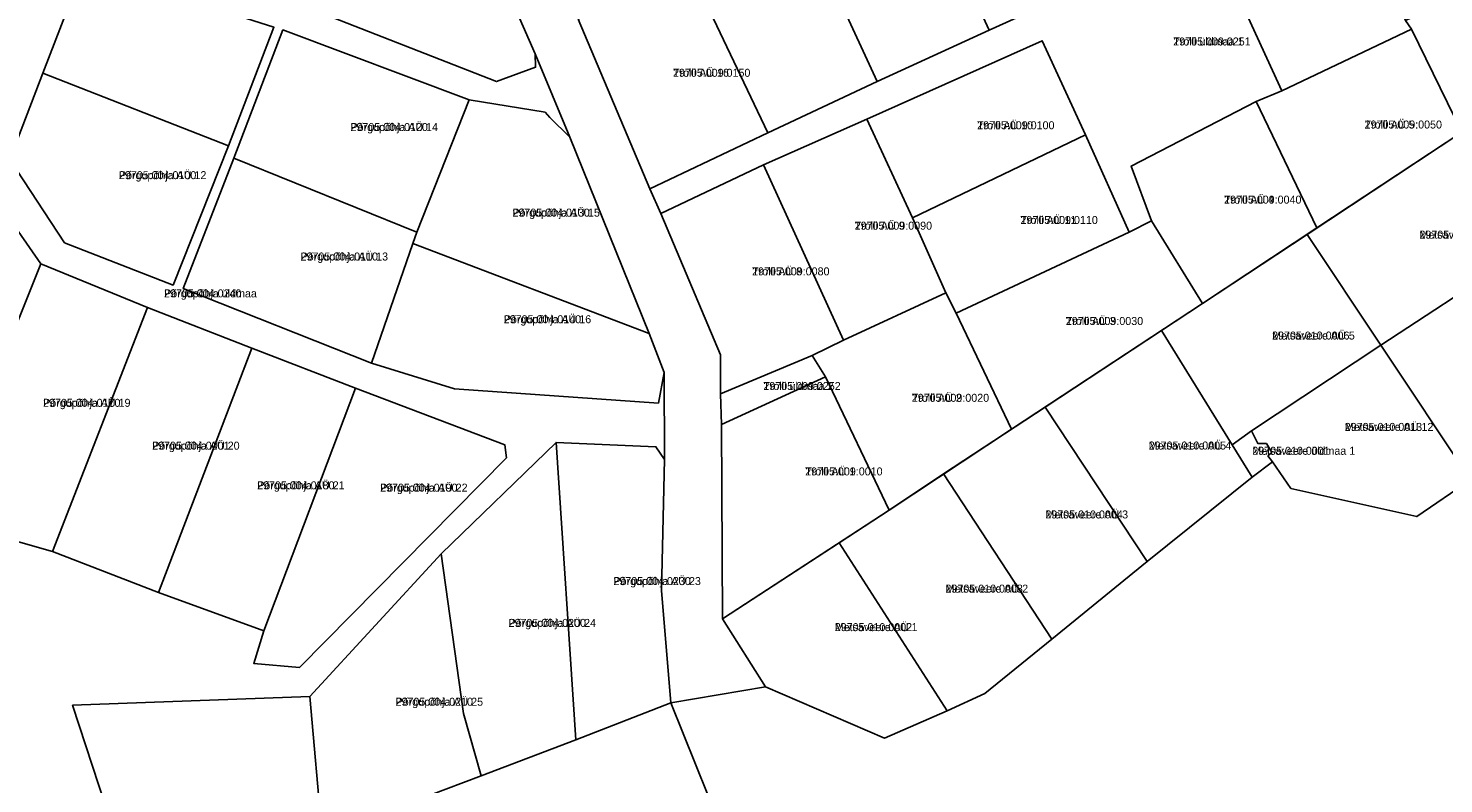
# Model space of a CAD drawing. Extents: x 504287 to 537970, y 6539941 to 6586214.
# Drawn here: x 519008.5 to 519273.8, y 6562862.8 to 6563004.5 of the extents above; entities that cross this region are included whole.
import ezdxf

# ---------------------------------------------------------------- set-up
doc = ezdxf.new("R2010")
doc.units = 0
for name, color, linetype in [('L_AADRESS', 7, 'Continuous'), ('PIIR', 7, 'Continuous'), ('TUNNUS', 7, 'Continuous')]:
    doc.layers.add(name, color=color, linetype=linetype)

msp = doc.modelspace()

# ---------------------------------------------------------------- linework, layer by layer
at = {"layer": 'PIIR'}
for points in [[(519283.83, 6563041.33), (519256.32, 6563029.03), (519256.88, 6563027.76), (519232.61, 6563016.49), (519243.47, 6562992.78), (519238.7, 6562990.76), (519215.28, 6562978.65), (519219.04, 6562968.38), (519214.9, 6562966.23), (519206.68, 6562984.48), (519198.6, 6563002.16), (519165.68, 6562987.42), (519146.31, 6562978.89), (519127.11, 6562969.74), (519125.05, 6562974.36), (519147.16, 6562984.86), (519167.63, 6562994.53), (519188.62, 6563004.14), (519209.25, 6563013.5), (519230.44, 6563023.1), (519230.89, 6563022.37), (519249.06, 6563030.62), (519267.25, 6563039.05), (519285.2, 6563047.67)], [(519005.08, 6562979.84), (519015.34, 6562964.24), (519035.67, 6562956.3), (519046.04, 6562982.44), (519054.56, 6563004.69), (519048.05, 6563006.78), (519031.71, 6563035.77), (519021.76, 6563023.32), (519001.51, 6563030.36)], [(519111.61, 6563006.2), (519125.05, 6562974.36), (519127.11, 6562969.74), (519138.31, 6562943.2), (519138.3, 6562935.88), (519138.44, 6562930.14), (519138.66, 6562893.71), (519146.7, 6562880.91), (519128.96, 6562877.92), (519127.19, 6562899.04), (519127.76, 6562923.57), (519127.7, 6562939.91), (519124.93, 6562947.2), (519110.03, 6562984.06), (519103.52, 6562999.7), (519089.19, 6563032.5)], [(519052.31, 6563011.78), (519096.3, 6562994.5), (519103.63, 6562997.17), (519103.52, 6562999.7), (519110.03, 6562984.06), (519106.32, 6562987.77), (519105.39, 6562988.78), (519091.18, 6562991.09), (519056.27, 6563004.18), (519047.08, 6562980.14), (519037.57, 6562955.65), (519072.89, 6562941.69), (519088.42, 6562936.85), (519126.64, 6562934.18), (519127.7, 6562939.91), (519127.76, 6562923.57), (519126.17, 6562925.98), (519107.47, 6562926.79), (519085.94, 6562905.88), (519061.33, 6562879.14), (519016.82, 6562877.48), (519029.17, 6562839.73)], [(518991.73, 6562912.38), (519013.07, 6562906.3), (519032.97, 6562898.65), (519052.71, 6562891.42), (519050.79, 6562885.32), (519059.36, 6562884.58), (519098.18, 6562923.93), (519097.88, 6562926.32), (519069.88, 6562936.94), (519050.44, 6562944.47), (519030.87, 6562952.08), (519010.88, 6562960.31), (519000.22, 6562975.6)], [(519145.17, 6562837.69), (519128.96, 6562877.92), (519146.7, 6562880.91), (519169.03, 6562871.31), (519180.74, 6562876.43), (519187.85, 6562879.66), (519200.41, 6562889.87), (519218.24, 6562904.47), (519237.96, 6562920.27), (519241.72, 6562923.17), (519245.19, 6562918.12), (519268.79, 6562912.88), (519278.84, 6562919.79)], [(519063.64, 6562853.01), (519093.44, 6562864.26), (519111.19, 6562871.01), (519128.96, 6562877.92), (519145.17, 6562837.69)]]:
    msp.add_lwpolyline(points, dxfattribs=at)
for points in [[(519174.27, 6563035.4), (519194.75, 6563045.14), (519209.25, 6563013.5), (519188.62, 6563004.14)], [(519021.76, 6563023.32), (519031.71, 6563035.77), (519048.05, 6563006.78), (519054.56, 6563004.69), (519046.04, 6562982.44), (519011.28, 6562996.06)], [(519153.28, 6563025.68), (519174.27, 6563035.4), (519188.62, 6563004.14), (519167.63, 6562994.53)], [(519050.19, 6563015.1), (519089.19, 6563032.5), (519103.52, 6562999.7), (519103.63, 6562997.17), (519096.3, 6562994.5), (519052.31, 6563011.78)], [(519001.51, 6563030.36), (519021.76, 6563023.32), (519011.28, 6562996.06), (519005.08, 6562979.84), (518985.05, 6562987.42)], [(519132.45, 6563015.78), (519153.28, 6563025.68), (519167.63, 6562994.53), (519147.16, 6562984.86)], [(519232.61, 6563016.49), (519256.88, 6563027.76), (519266.68, 6563005.97), (519267.83, 6563004.34), (519243.47, 6562992.78)], [(519267.83, 6563004.34), (519266.68, 6563005.97), (519294.48, 6563019.19), (519295.89, 6563016.27), (519300.23, 6563018.09), (519306.55, 6563004.35), (519277.21, 6562985.01)], [(519111.61, 6563006.2), (519132.45, 6563015.78), (519147.16, 6562984.86), (519125.05, 6562974.36)], [(519056.27, 6563004.18), (519091.18, 6562991.09), (519081.34, 6562966.23), (519047.08, 6562980.14)], [(519165.68, 6562987.42), (519198.6, 6563002.16), (519206.68, 6562984.48), (519174.29, 6562968.91)], [(519238.7, 6562990.76), (519243.47, 6562992.78), (519267.83, 6563004.34), (519277.21, 6562985.01), (519250.06, 6562967.02)], [(519005.08, 6562979.84), (519011.28, 6562996.06), (519046.04, 6562982.44), (519035.67, 6562956.3), (519015.34, 6562964.24)], [(519081.34, 6562966.23), (519091.18, 6562991.09), (519105.39, 6562988.78), (519106.32, 6562987.77), (519110.03, 6562984.06), (519124.93, 6562947.2), (519080.63, 6562964.11)], [(519219.04, 6562968.38), (519215.28, 6562978.65), (519238.7, 6562990.76), (519250.06, 6562967.02), (519228.6, 6562952.85)], [(519146.31, 6562978.89), (519165.68, 6562987.42), (519174.29, 6562968.91), (519180.54, 6562954.87), (519161.32, 6562946)], [(519180.54, 6562954.87), (519174.29, 6562968.91), (519206.68, 6562984.48), (519214.9, 6562966.23), (519182.46, 6562951.06)], [(519248.26, 6562965.83), (519277.21, 6562985.01), (519290.46, 6562963.94), (519285.76, 6562960.55), (519262.08, 6562945.02)], [(518994.98, 6562978.08), (519000.22, 6562975.6), (519010.88, 6562960.31), (518991.73, 6562912.38), (518972.83, 6562917.66)], [(519047.08, 6562980.14), (519081.34, 6562966.23), (519080.63, 6562964.11), (519072.89, 6562941.69), (519037.57, 6562955.65)], [(519138.31, 6562943.2), (519127.11, 6562969.74), (519146.31, 6562978.89), (519161.32, 6562946), (519155.45, 6562943.1), (519138.3, 6562935.88)], [(519182.46, 6562951.06), (519214.9, 6562966.23), (519219.04, 6562968.38), (519228.6, 6562952.85), (519192.81, 6562929.26)], [(519234.2, 6562926.35), (519220.92, 6562947.79), (519228.6, 6562952.85), (519248.26, 6562965.83), (519262.08, 6562945.02), (519237.82, 6562928.96)], [(519072.89, 6562941.69), (519080.63, 6562964.11), (519124.93, 6562947.2), (519127.7, 6562939.91), (519126.64, 6562934.18), (519088.42, 6562936.85)], [(519010.88, 6562960.31), (519030.87, 6562952.08), (519013.07, 6562906.3), (518991.73, 6562912.38)], [(519262.08, 6562945.02), (519285.76, 6562960.55), (519302.59, 6562936.49), (519278.84, 6562919.79)], [(519157.96, 6562939.1), (519155.45, 6562943.1), (519161.32, 6562946), (519180.54, 6562954.87), (519182.46, 6562951.06), (519192.81, 6562929.26), (519169.88, 6562914.11)], [(519030.87, 6562952.08), (519050.44, 6562944.47), (519032.97, 6562898.65), (519013.07, 6562906.3)], [(519220.92, 6562947.79), (519234.2, 6562926.35), (519237.96, 6562920.27), (519218.24, 6562904.47), (519199.11, 6562933.41)], [(519050.44, 6562944.47), (519069.88, 6562936.94), (519052.71, 6562891.42), (519032.97, 6562898.65)], [(519241.72, 6562923.17), (519240.88, 6562924.25), (519241.61, 6562924.89), (519240.61, 6562926.56), (519238.99, 6562926.6), (519237.82, 6562928.96), (519262.08, 6562945.02), (519278.84, 6562919.79), (519268.79, 6562912.88), (519245.19, 6562918.12)], [(519138.3, 6562935.88), (519155.45, 6562943.1), (519157.96, 6562939.1), (519138.44, 6562930.14)], [(519138.44, 6562930.14), (519157.96, 6562939.1), (519169.88, 6562914.11), (519138.66, 6562893.71)], [(519050.79, 6562885.32), (519052.71, 6562891.42), (519069.88, 6562936.94), (519097.88, 6562926.32), (519098.18, 6562923.93), (519059.36, 6562884.58)], [(519180.11, 6562920.87), (519199.11, 6562933.41), (519218.24, 6562904.47), (519200.41, 6562889.87)], [(519234.2, 6562926.35), (519237.82, 6562928.96), (519238.99, 6562926.6), (519240.61, 6562926.56), (519241.61, 6562924.89), (519240.88, 6562924.25), (519241.72, 6562923.17), (519237.96, 6562920.27)], [(519090.13, 6562875.93), (519085.94, 6562905.88), (519107.47, 6562926.79), (519111.19, 6562871.01), (519093.44, 6562864.26)], [(519107.47, 6562926.79), (519126.17, 6562925.98), (519127.76, 6562923.57), (519127.19, 6562899.04), (519128.96, 6562877.92), (519111.19, 6562871.01)], [(519169.88, 6562914.11), (519180.11, 6562920.87), (519200.41, 6562889.87), (519187.85, 6562879.66), (519180.74, 6562876.43), (519160.5, 6562907.98)], [(519138.66, 6562893.71), (519160.5, 6562907.98), (519180.74, 6562876.43), (519169.03, 6562871.31), (519146.7, 6562880.91)], [(519061.33, 6562879.14), (519085.94, 6562905.88), (519090.13, 6562875.93), (519093.44, 6562864.26), (519063.64, 6562853.01)], [(519016.82, 6562877.48), (519061.33, 6562879.14), (519063.64, 6562853.01), (519029.17, 6562839.73)]]:
    msp.add_lwpolyline(points, close=True, dxfattribs=at)

# ---------------------------------------------------------------- texts
at = {"layer": 'L_AADRESS'}
for s, p in [('Trolli üldmaa 1', (519223.15, 6563001.26)), ('Trolli AÜ 16', (519129.38, 6562995.39)), ('Põrgupõhja AÜ 14', (519068.93, 6562985.21)), ('Trolli AÜ 10', (519186.38, 6562985.54)), ('Trolli AÜ 5', (519259.01, 6562985.68)), ('Põrgupõhja AÜ 12', (519025.52, 6562976.18)), ('Trolli AÜ 4', (519232.67, 6562971.59)), ('Põrgupõhja AÜ 15', (519099.28, 6562969.15)), ('Trolli AÜ 9', (519163.43, 6562966.7)), ('Trolli AÜ 11', (519194.5, 6562967.77)), ('Metsaveere AÜ 6', (519269.29, 6562965.02)), ('Põrgupõhja AÜ 13', (519059.57, 6562960.92)), ('Trolli AÜ 8', (519144.21, 6562958.13)), ('Põrgupõhja üldmaa', (519033.98, 6562954)), ('Põrgupõhja AÜ 16', (519097.65, 6562949.15)), ('Trolli AÜ 3', (519203, 6562948.82)), ('Metsaveere AÜ 5', (519241.67, 6562946.09)), ('Trolli üldmaa 2', (519146.31, 6562936.62)), ('Trolli AÜ 2', (519174.13, 6562934.41)), ('Põrgupõhja AÜ 19', (519011.3, 6562933.47)), ('Metsaveere AÜ 12', (519255.29, 6562928.95)), ('Põrgupõhja AÜ 20', (519031.75, 6562925.43)), ('Metsaveere AÜ 4', (519218.54, 6562925.46)), ('Metsaveere üldmaa 1', (519237.96, 6562924.47)), ('Trolli AÜ 1', (519154.16, 6562920.6)), ('Põrgupõhja AÜ 21', (519051.43, 6562917.99)), ('Põrgupõhja AÜ 22', (519074.48, 6562917.55)), ('Metsaveere AÜ 3', (519199.18, 6562912.53)), ('Põrgupõhja AÜ 23', (519118.21, 6562900.03)), ('Metsaveere AÜ 2', (519180.45, 6562898.61)), ('Põrgupõhja AÜ 24', (519098.56, 6562892.18)), ('Metsaveere AÜ 1', (519159.7, 6562891.39)), ('Põrgupõhja AÜ 25', (519077.38, 6562877.39))]:
    msp.add_text(s, height=1.5, dxfattribs=at).set_placement(p)
at = {"layer": 'TUNNUS'}
for s, p in [('29705:009:0251', (519223.15, 6563001.26)), ('29705:009:0150', (519129.38, 6562995.39)), ('29705:004:0120', (519068.93, 6562985.21)), ('29705:009:0100', (519186.38, 6562985.54)), ('29705:009:0050', (519259.01, 6562985.68)), ('29705:004:0100', (519025.52, 6562976.18)), ('29705:009:0040', (519232.67, 6562971.59)), ('29705:004:0130', (519099.28, 6562969.15)), ('29705:009:0090', (519163.43, 6562966.7)), ('29705:009:0110', (519194.5, 6562967.77)), ('29705:010:0007', (519269.29, 6562965.02)), ('29705:004:0110', (519059.57, 6562960.92)), ('29705:009:0080', (519144.21, 6562958.13)), ('29705:004:0240', (519033.98, 6562954)), ('29705:004:0140', (519097.65, 6562949.15)), ('29705:009:0030', (519203, 6562948.82)), ('29705:010:0006', (519241.67, 6562946.09)), ('29705:009:0252', (519146.31, 6562936.62)), ('29705:009:0020', (519174.13, 6562934.41)), ('29705:004:0170', (519011.3, 6562933.47)), ('29705:010:0013', (519255.29, 6562928.95)), ('29705:004:0001', (519031.75, 6562925.43)), ('29705:010:0005', (519218.54, 6562925.46)), ('29705:010:0001', (519237.96, 6562924.47)), ('29705:009:0010', (519154.16, 6562920.6)), ('29705:004:0180', (519051.43, 6562917.99)), ('29705:004:0190', (519074.48, 6562917.55)), ('29705:010:0004', (519199.18, 6562912.53)), ('29705:004:0230', (519118.21, 6562900.03)), ('29705:010:0003', (519180.45, 6562898.61)), ('29705:004:0200', (519098.56, 6562892.18)), ('29705:010:0002', (519159.7, 6562891.39)), ('29705:004:0210', (519077.38, 6562877.39))]:
    msp.add_text(s, height=1.5, dxfattribs=at).set_placement(p)

doc.saveas('drawing.dxf')
